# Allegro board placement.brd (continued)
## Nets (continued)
DATA1.VD3: RN3.4 U1.N1
DATA1.VD4: RN2.1 U1.P2
DATA1.VD5: RN2.2 U1.P1
DATA1.VD6: RN2.3 U1.R2
DATA1.VD7: RN2.4 U1.R1
DATA1.WSTAT_L: U1.J6 U22.11
DATA2+: U1.B5 U2.D6
DATA2-: U1.A5 U2.C6
DATA3+: U1.D5 U2.B6
DATA3-: U1.C5 U2.A6
DATA.BA0: U1.H16 U6.13 U8.2 U9.13
DATA.BA1: U1.H15 U6.14 U8.3 U9.14
DATA.BA2: U1.G14 U6.16 U8.5 U9.16
DATA.BA3: U1.G16 U6.17 U8.6 U9.17
DATA.BD0: U1.F16 U9.2
DATA.BD1: U1.F15 U9.3
DATA.BD2: U1.E16 U9.5
DATA.BD3: U1.E15 U9.6
DATA.BD4: U1.E13 U9.8
DATA.BD5: U1.E12 U9.9
DATA.BD6: U1.B15 U9.11
DATA.BD7: U1.B16 U9.12
DATA.BD8: U1.F12 U6.2 U8.23
DATA.BD9: U1.G11 U6.3 U8.22
DATA.BD12: U1.F13 U6.8 U8.17
DATA.BD13: U1.F14 U6.9 U8.16
DATA.BD14: U1.C15 U6.11 U8.14
DATA.BD15: U1.C16 U6.12 U8.13
DATA.CLKB: J6.E16 U1.J16
DDIR: U6.1 U7.1 U8.24 U9.1
DDR_A0: U2.C1 U12.M8 U13.M8
DDR_A1: U2.D1 U12.M3 U13.M3
DDR_A2: U2.E1 U12.M7 U13.M7
DDR_A3: U2.F1 U12.N2 U13.N2
DDR_A4: U2.G1 U12.N8 U13.N8
DDR_A5: U2.H1 U12.N3 U13.N3
DDR_A6: U2.J1 U12.N7 U13.N7
DDR_A7: U2.K1 U12.P2 U13.P2
DDR_A8: U2.L1 U12.P8 U13.P8
DDR_A9: U2.M1 U12.P3 U13.P3
DDR_A10: U2.N1 U12.M2 U13.M2
DDR_A11: U2.P1 U12.P7 U13.P7
DDR_A12: U2.R1 U12.R2 U13.R2
DDR_BA0: U2.M2 U12.L2 U13.L1
DDR_BA1: U2.P2 U12.L3 U13.L3
DDR_BA2: U2.R2 U12.L1 U13.L2
DDR_DQ0: U2.F5 U12.G8
DDR_DQ1: U2.C2 U12.G2
DDR_DQ2: U2.F4 U12.H7
DDR_DQ3: U2.E4 U12.H3
DDR_DQ4: U2.D3 U12.H1
DDR_DQ5: U2.G5 U12.H9
DDR_DQ6: U2.C3 U12.F1
DDR_DQ7: U2.G3 U12.F9
DDR_DQ8: U2.E2 U12.C8
DDR_DQ9: U2.B3 U12.C2
DDR_DQ10: U2.F3 U12.D7
DDR_DQ11: U2.B1 U12.D3
DDR_DQ12: U2.B2 U12.D1
DDR_DQ13: U2.F2 U12.D9
DDR_DQ14: U2.A2 U12.B1
DDR_DQ15: U2.E3 U12.B9
DDR_DQ16: U2.L3 U13.G8
DDR_DQ17: U2.H5 U13.G2
DDR_DQ18: U2.K5 U13.H7
DDR_DQ19: U2.K2 U13.H3
DDR_DQ20: U2.H3 U13.H1
DDR_DQ21: U2.L5 U13.H9
DDR_DQ22: U2.H2 U13.F1
DDR_DQ23: U2.M4 U13.F9
DDR_DQ24: U2.M5 U13.C8
DDR_DQ25: U2.J3 U13.C2
DDR_DQ26: U2.L4 U13.D7
DDR_DQ27: U2.K3 U13.D3
DDR_DQ28: U2.H4 U13.D1
DDR_DQ29: U2.N3 U13.D9
DDR_DQ30: U2.J4 U13.B1
DDR_DQ31: U2.N4 U13.B9
DDS.DATA0: U2.B10 U4.4
DDS.DATA1: U2.C10 U4.3
DDS.DATA2: U2.E10 U4.2
DDS.DATA3: U2.F10 U4.1
DDS.DATA4: U2.E11 U4.28
DDS.DATA5: U2.D11 U4.27
DDS.DATA6: U2.C11 U4.26
DDS.DATA7: U2.A11 U4.25
DDS.FQUD: U2.B12 U4.8
DDS.RESET: U2.A13 U4.22
DDS.WCLK: U2.A14 U4.7
DDS_CLK: L4.2 U4.9
DDS_OUT: C34.2 C36.2 L5.1 U4.20
DEN/: U6.48 U7.17 U9.48
DHEN/: U7.18 U8.25(G\)
DI: P1.7 U1.C12
DIFF1+: U1.D16 U6.5 U8.20
DIFF1-: U1.D14 U6.6 U8.19
DQ0: U32.19 U38.12
DQ1: U32.18 U38.13
DQ2: U32.17 U38.14
DQ3: U32.16 U38.15
DQ4: U32.15 U38.16
DQ5: U32.14 U38.17
DQ6: U32.13 U38.18
DQ7: U32.12 U38.19
DQ8: U35.19 U39.12
DQ9: U35.18 U39.13
DQ10: U35.17 U39.14
DQ11: U35.16 U39.15
DQ12: U35.15 U39.16
DQ13: U35.14 U39.17
DQ14: U35.13 U39.18
DQ15: U35.12 U39.19
FPGA/: U7.15 U48.5
GAIN: U1.J4 U33.6 U36.6
HS/: U7.16 U48.4
JTAG_D0: P1.8 U2.E14
LED1: Q4.1 R31.2
LED2: Q5.1 R32.2
LED3: Q6.1 R33.2
LED4: Q7.1 R34.2
LPF_OUT: C42.1 R17.2 R18.2
MEMORY.CTRL.RCS0: J7.26 U1.J1 U40.22 U44.22
MEMORY.CTRL.RCS1: J7.76 U1.G3 U41.22 U45.22
MEMORY.CTRL.RCS2: J7.126 U1.F2 U42.22 U46.22
MEMORY.CTRL.RCS3: J7.176 U1.G6 U43.22 U47.22
MEMORY.CTRL.RWE: J7.27 J7.77 J7.127 J7.177 U1.M11 U40.29(W\E\) U41.29(W\E\) U42.29(W\E\) U43.29(W\E\) U44.29(W\E\) U45.29(W\E\) U46.29(W\E\) U47.29(W\E\)
MEMORY.RA0: J7.1 J7.51 J7.101 J7.151 U1.P5 U40.12 U41.12 U42.12 U43.12 U44.12 U45.12 U46.12 U47.12
MEMORY.RA1: J7.2 J7.52 J7.102 J7.152 U1.P10 U40.11 U41.11 U42.11 U43.11 U44.11 U45.11 U46.11 U47.11
MEMORY.RA2: J7.3 J7.53 J7.103 J7.153 U1.N11 U40.10 U41.10 U42.10 U43.10 U44.10 U45.10 U46.10 U47.10
MEMORY.RA3: J7.4 J7.54 J7.104 J7.154 U1.R9 U40.9 U41.9 U42.9 U43.9 U44.9 U45.9 U46.9 U47.9
MEMORY.RA4: J7.5 J7.55 J7.105 J7.155 U1.P8 U40.8 U41.8 U42.8 U43.8 U44.8 U45.8 U46.8 U47.8
MEMORY.RA5: J7.6 J7.56 J7.106 J7.156 U1.R7 U40.7 U41.7 U42.7 U43.7 U44.7 U45.7 U46.7 U47.7
MEMORY.RA6: J7.7 J7.57 J7.107 J7.157 U1.P6 U40.6 U41.6 U42.6 U43.6 U44.6 U45.6 U46.6 U47.6
MEMORY.RA7: J7.8 J7.58 J7.108 J7.158 U1.N5 U40.5 U41.5 U42.5 U43.5 U44.5 U45.5 U46.5 U47.5
MEMORY.RA8: J7.9 J7.59 J7.109 J7.159 U1.L8 U40.27 U41.27 U42.27 U43.27 U44.27 U45.27 U46.27 U47.27
MEMORY.RA9: J7.10 J7.60 J7.110 J7.160 U1.M6 U40.26 U41.26 U42.26 U43.26 U44.26 U45.26 U46.26 U47.26
MEMORY.RA10: J7.11 J7.61 J7.111 J7.161 U1.T10 U40.23 U41.23 U42.23 U43.23 U44.23 U45.23 U46.23 U47.23
MEMORY.RA11: J7.12 J7.62 J7.112 J7.162 U1.P11 U40.25 U41.25 U42.25 U43.25 U44.25 U45.25 U46.25 U47.25
MEMORY.RA12: J7.13 J7.63 J7.113 J7.163 U1.T9 U40.4 U41.4 U42.4 U43.4 U44.4 U45.4 U46.4 U47.4
MEMORY.RA13: J7.14 J7.64 J7.114 J7.164 U1.T8 U40.28 U41.28 U42.28 U43.28 U44.28 U45.28 U46.28 U47.28
MEMORY.RA14: J7.15 J7.65 J7.115 J7.165 U1.T7 U40.3 U41.3 U42.3 U43.3 U44.3 U45.3 U46.3 U47.3
MEMORY.RA15: J7.16 J7.66 J7.116 J7.166 U1.T6 U40.31 U41.31 U42.31 U43.31 U44.31 U45.31 U46.31 U47.31
MEMORY.RA16: J7.17 J7.67 J7.117 J7.167 U40.2 U41.2 U42.2 U43.2 U44.2 U45.2 U46.2 U47.2
MEMORY.RD0: J7.18 J7.68 J7.118 J7.168 P2.6 U1.R15 U40.13 U41.13 U42.13 U43.13 U44.13 U45.13 U46.13 U47.13
MEMORY.RD1: J7.19 J7.69 J7.119 J7.169 P2.4 U1.R16 U40.14 U41.14 U42.14 U43.14 U44.14 U45.14 U46.14 U47.14
MEMORY.RD2: J7.20 J7.70 J7.120 J7.170 P2.2 U1.R14 U40.15 U41.15 U42.15 U43.15 U44.15 U45.15 U46.15 U47.15
MEMORY.RD3: J7.21 J7.71 J7.121 J7.171 P2.1 U1.T15 U40.17 U41.17 U42.17 U43.17 U44.17 U45.17 U46.17 U47.17
MEMORY.RD4: J7.22 J7.72 J7.122 J7.172 P2.3 U1.T14 U40.18 U41.18 U42.18 U43.18 U44.18 U45.18 U46.18 U47.18
MEMORY.RD5: J7.23 J7.73 J7.123 J7.173 P2.5 U1.T13 U40.19 U41.19 U42.19 U43.19 U44.19 U45.19 U46.19 U47.19
MEMORY.RD6: J7.24 J7.74 J7.124 J7.174 P2.7 U1.R12 U40.20 U41.20 U42.20 U43.20 U44.20 U45.20 U46.20 U47.20
MEMORY.RD7: J7.25 J7.75 J7.125 J7.175 P2.8(PIN8) U1.T12 U40.21 U41.21 U42.21 U43.21 U44.21 U45.21 U46.21 U47.21
MRD/: J6.E4 U7.8
MWR/: J6.E5 U7.9
N00036_USER_DESIGN_OUTPUTS0_D_1: L8.2 R53.1 R54.1 U32.5 U32.8 U33.5(VL)
N00036_USER_DESIGN_OUTPUTS0_DAA: L10.2 R55.1 R56.1 U35.5 U35.8 U36.5(VL)
N00038_USER_DESIGN_OUTPUTS0_D_1: C198.1 L7.2 U32.4
N00038_USER_DESIGN_OUTPUTS0_DAA: C201.1 L9.2 U35.4
N00044_USER_DESIGN_OUTPUTS0_D_1: U36.1 U37.2
N00044_USER_DESIGN_OUTPUTS0_DAA: U33.1 U34.2
N00046_USER_DESIGN_OUTPUTS0_D_1: R54.2 U33.8
N00046_USER_DESIGN_OUTPUTS0_DAA: R56.2 U36.8
N00048_USER_DESIGN_OUTPUTS0_D_1: R53.2 U33.2
N00048_USER_DESIGN_OUTPUTS0_DAA: R55.2 U36.2
N00060_USER_DESIGN_OUTPUTS0_D_1: U35.6 U37.3
N00060_USER_DESIGN_OUTPUTS0_DAA: U32.6 U34.3
PGOOD: R2012.2 U51.9
Q1E: Q9.2(E) R52.2
Q2E: C68.2 Q8.2 R45.1 R47.2
RDY/: J6.E6 U7.19
RESET: R2008.2 U1.M12 U2.T11 U49.2 U50.11
RESET/: J6.E1 U48.3
SEL: U7.11 U48.9
SHIELD1: J5.10
SHIELD2: J5.11
STDA_SSRX+: C2003.1 R2002.2 U2.A8
STDA_SSRX-: C2002.1 R2003.2 U2.B8
STDA_SSTX+: C2004.1 R2005.2 U2.E7
STDA_SSTX-: C2005.1 R2004.2 U2.E8
TCLK: P1.3 U1.C14 U2.C14
TDO: U1.E14 U2.C12
TMS: P1.11 U1.A15 U2.A15
V+12: C31.2 C32.2 C33.2 C39.2 C62.1 C64.1 C66.1 C199.1 C202.1 D5.1 J6.A1 J6.A2 J6.D1 J6.D2 R19.2 R45.2 U3.8 U5.1 U29.J1 U29.J2 U29.J3 U29.K1 U29.K2 U29.K3 U29.L1 U29.L2 U29.L3 U29.L5 U30.J1 U30.J2 U30.J3 U30.K1 U30.K2 U30.K3 U30.L1 U30.L2 U30.L3 U30.L5 U31.J1 U31.J2 U31.J3 U31.K1 U31.K2 U31.K3 U31.L1 U31.L2 U31.L3 U31.L5 U33.4 U34.7 U36.4 U37.7
VCLKC: R26.2 U39.11
VDX0: R8.2 RN2.5(2) U22.9 U38.9 U39.9 U48.11
VDX1: R6.2 RN2.6 U22.8 U38.8 U39.8 U48.12
VDX2: R4.2 RN2.7 U22.7 U38.7 U39.7 U48.13
VDX3: R2.2 RN2.8 U22.6 U38.6 U39.6 U48.14
VDX4: R7.2 RN3.5(2) U22.5 U38.5 U39.5 U48.15
VDX5: R5.2 RN3.6 U22.4 U38.4 U39.4 U48.16
VDX6: R3.2 RN3.7 U22.3 U38.3 U39.3 U48.17
VDX7: R1.2 RN3.8 U22.2 U38.2 U39.2 U48.18
VTTREF: C2016.1 U51.6
WAIT/: J6.E2 U48.2
N00286: C34.1 C35.1 C38.1 L5.2 L6.1
N00395: C35.2 C37.2 L6.2 R17.1
N00671: C3.1 R1.1
N00689: C5.1 R3.1
N00703: C7.1 R5.1
N00717: C9.1 R7.1
N00827: C4.1 R2.1
N00831: C6.1 R4.1
N00835: C8.1 R6.1
N00837: C10.1 R8.1
N04966: L7.1 L9.1
N15853: U2.T7 U12.K9
N15863: U2.R7 U13.K9
N15891: U2.M7 U12.B3
N15907: U2.P6 U12.F3
N15924: U2.N6 U13.F3
N15963: U2.L7 U13.B3
N16041: U2.T5 U12.J8 U13.J8
N16054: U2.R5 U12.K8 U13.K8
N16064: U2.T4 U12.K2 U13.K2
N16300: U2.P5 U12.L8
N16316: U2.N5 U13.L8
N16670: U2.P8 U12.K3 U13.K3
N16714: U2.P7 U12.K7 U13.K7
N16747: U2.T3 U12.L7 U13.L7
N17275: U2.R9 U12.B7
N17319: U2.T9 U12.A8
N17344: U2.N9 U13.A8
N17369: U2.P9 U13.B7
N17394: U2.M6 U12.F7
N17449: U2.T6 U13.F7
N44457: U1.K6 U10.8
N44464: U1.K3 U10.3 U10.13
N44478: U1.E2 U10.7
N44485: U1.L4 U10.10
N44490: U1.L5 U10.1
N45317: U2.M11 U11.1
N61996: C71.1 R50.2
N62056: Q8.1 R46.1 R51.1
N62230: C71.2 Q9.1 R48.1 R49.1
N62316: C72.2 Q8.3(E) R48.2
N62436: D5.3(C) R46.2
N62564: C69.1 C70.1 Q9.3 R47.1
N68133: C42.2 Q3.1 R21.1 R23.2
N70364: C43.2 Q3.2(E) R24.2
N80550: C40.2 R19.1
N81780: C69.2 R49.2
N84247: U6.22 U8.9 U8.12 U9.20
N103899: U6.19 U6.23 U8.8 U8.11 U9.19 U9.23
N108857: R12.2 U4.21
N108997: R14.2 U4.12
N111502: C11.1 C12.2 U3.1(OUT)
N111881: C11.2 C13.2 C14.2 R9.2 R10.2 R11.1
N113142: C15.2 L4.1 R9.1
N114006: C18.1 C20.1 Q1.1 R10.1 R13.2
N118214: C19.1 L3.3(OUT2) Q1.3
N118917: C16.2 L3.1 R11.2
N120412: C17.1 L3.2
N121910: C20.2 C21.2 Q1.2(E) R15.2
N123723: C17.2 Q2.3 R16.2
N124926: C19.2 C21.1 C22.2 Q2.1 R13.1 R15.1 R16.1 XTAL1.3
N129422: C22.1 L4.3(OUT2) Q2.2(S)
N221560: C18.2 XTAL1.4
N277989: Q3.3
N828385: R31.1 U22.19
N829333: R43.1 U31.G7
N829669: R44.1 U31.K7
N829685: U31.G5 U31.H5
N830942: D3.A R29.2
N831005: D3.C Q6.3
N831029: R39.1 U29.G7
N831181: R40.1 U29.K7
N831646: D2.A R28.2
N831650: D2.C Q5.3
N831853: R41.1 U30.G7
N831855: D1.A R27.2
N831859: D1.C Q4.3
N832005: R42.1 U30.K7
N832074: D4.A R30.2
N832078: D4.C Q7.3
N852308: R32.1 U22.17
N852494: R33.1 U22.15
N852683: R34.1 U22.13
N884986: C70.2 J3.1
N885188: C2.1 J2.1 L2.2
N885276: C1.1 J1.1 L1.2
N885442: L1.1 U34.6
N1358395: J5.6 R2003.1
N1358407: J5.8 R2004.1
N1358411: J5.9 R2005.1
N1358515: J5.2 R2000.1
N1358527: J5.3 R2001.1
N1358539: J5.5 R2002.1
N1406173: R2009.1 U50.9(XTAL2) Y1.3(OUTPUT)
N1406200: R2009.2 U50.8 Y1.1
N1406547: C2008.1 C2009.1 R2006.2 U50.4 U50.5
N1406997: R2007.1 U50.10 U50.19 U50.21
N1421557: L2.1 U37.6
N1432081: U2.M12 U11.8
N1432096: U2.R11 U11.3
N1432111: U2.P10 U11.7
N1432121: U2.T10 U11.10
N1438447: SW2.2 U49.3
N1472359: C2010.1 R2010.2 R2011.1 U51.1
N2993541: C43.1 R25.2

Pads without a net: D5 2; J6 A5 A6 A7 A8 A9 A10 A11 A12 A13 A14 A15 A16 A17 A18 A19 A20 A21 A22 C3 C4 C5 C6 C7 C8 C9 C10 C11 C12 C13 C14 C15 C16 C17 C18 C19 C20 C21 C22 D5 D6 D7 D8 D9 D10 D11 D12 D13 D14 D15 D16 D17 D18 D19 D20 D21 D22 E7 F3 F4 F5 F6 F7 F8 F9 F10 F11 F12 F13 F14 F15 F16 F17 F18 F19 F20 F21 F22; J7 28 29 30 78 79 80 128 129 130 178 179 180; P1 10; SW2 3 4; U1 A2 A3 A4 A7 A8 A9 A10 A11 A12 A13 A14 B1 B2 B3 B8 B10 B12 B14 C1 C2 C4 C7 C8 C9 C10 C11 C13 D1 D3 D8 D9 D11 D12 E1 E3 E4 E6 E7 E8 E10 E11 F1 F3 F4 F5 F6 F7 F9 F10 G1 G5 G12 H1 H2 H5 H11 H13 H14 J3 J11 J12 J13 J14 K1 K2 K11 K12 K14 K15 K16 L1 L3 L7 L10 L11 L12 L13 L14 L16 M3 M4 M5 M7 M10 M13 M14 M15 M16 N4 N6 N9 N12 N14 N16 P4 P7 P9 P12 P13 P14 P15 P16 R3 R5 T2 T3 T4 T5; U2 A3 A4 A7 A9 A10 A12 B14 B15 B16 C4 C7 C8 C9 C13 C15 C16 D8 D9 D12 D14 D16 E6 E12 E13 E15 E16 F6 F7 F9 F12 F13 F14 F15 F16 G6 G11 G12 G14 G16 H11 H13 H14 H15 H16 J6 J13 J14 J16 K6 K11 K12 K14 K15 K16 L8 L10 L11 L12 L13 L14 L16 M3 M9 M10 M13 M14 M15 M16 N8 N12 N14 N16 P4 P12 P13 P14 P15 P16 R3 R12 R14 R15 R16 T2 T8 T12 T13 T14 T15; U3 4 5; U4 13 14 15 16 17; U6 20; U9 22; U10 2 4 5 6 9 12 14 15 16 17; U11 2 4 5 6 9 12 13 14 15 16 17; U12 A2 E2 E8 G3 R3 R7 R8; U13 A2 E2 E8 G3 R3 R7 R8; U22 12 14 16 18; U29 G5 H7 J7; U30 G5 H7 J7; U31 H7 J7; U34 1 5 8; U37 1 5 8; U40 1 30; U41 1 30; U42 1 30; U43 1 30; U44 1 30; U45 1 30; U46 1 30; U47 1 30; U48 1 19; U50 6 7 16 24 26; XTAL1 5; Y1 2 4

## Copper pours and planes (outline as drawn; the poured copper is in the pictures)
GND EARTH on TOP (solid shape): 124.87,24.04 124.87,16.51 117.25,16.51 117.25,19.05 119.64,19.05 122.97,20.32 119.64,21.59 117.63,21.59 116.26,20.23 114.23,20.23 114.23,24.04 114.48,24.29 124.62,24.29
GND EARTH on TOP (solid shape): 124.87,8.56 124.87,1.04 117.25,1.04 117.25,3.58 119.64,3.58 122.97,4.85 119.64,6.12 117.63,6.12 116.26,4.75 114.23,4.75 114.23,8.56 114.48,8.81 124.62,8.81
Net_5 on TOP (solid shape): 9.62,107.11 9.63,107.07 9.63,107 9.63,106.88 9.63,106.17 9.63,104.94 9.64,103.66 9.64,103.53 9.65,103.38 9.63,103.21 9.61,103.19 9.56,103.19 9.44,103.19 9.26,103.18 9.05,103.18 8.83,103.18 8.43,103.19 8.22,103.19 7.5,104.25 7.49,104.43 7.48,104.59 7.48,104.71 8.13,104.71 8.13,104.67 8.21,104.1 8.23,104.03 8.26,103.97 8.29,103.91 8.32,103.86 8.35,103.81 8.39,103.77 8.48,103.71 8.88,103.67 8.95,103.73 8.95,105.29 8.92,105.38 8.81,105.59 8.75,105.64 8.7,105.7 8.61,105.7 8.54,105.7 8.43,105.66 8.38,105.61 8.35,105.58 8.32,105.55 8.3,105.51 8.27,105.47 8.25,105.43 8.24,105.39 8.22,105.35 8.16,105 8.13,104.75 8.13,104.71 7.48,104.71 7.48,104.79 7.48,104.88 7.49,104.96 7.49,105.04 7.5,105.1 7.5,105.16 7.52,105.26 8.91,106.08 8.95,106.36 8.95,107.09 9.49,107.16
Net_6 on TOP (solid shape): 5.7,106.11 6,105.59 6.05,105.42 6.06,103.98 6.06,103.84 6.06,103.72 6.06,103.46 6.09,103.28 6.09,103.25 6.08,103.22 6.05,103.2 6,103.19 5.91,103.19 5.78,103.18 5.16,103.18 4.98,103.18 4.84,103.19 4.74,103.19 4.66,103.2 4.6,103.21 4.56,103.22 4.47,103.26 4.42,103.29 4.38,103.32 4.34,103.34 4.31,103.38 4.27,103.41 4.22,103.48 4.17,103.56 4.05,104.09 4.05,104.13 4.69,104.13 4.69,104.08 4.71,103.97 5.06,103.67 5.16,103.67 5.24,103.67 5.35,103.7 5.38,103.73 5.4,103.99 5.4,104.44 5.39,104.68 5.38,104.7 5.22,104.72 5.16,104.71 4.77,104.47 4.74,104.43 4.73,104.39 4.71,104.35 4.7,104.3 4.69,104.24 4.69,104.19 4.69,104.13 4.05,104.13 4.06,104.26 4.08,104.39 4.15,104.57 4.19,104.65 5.04,105.15 5.09,105.16 5.37,105.33 5.35,105.41 5.34,105.47 5.31,105.53 5.29,105.59 5.25,105.63 5.21,105.67 5.17,105.7 5.06,105.75 4.99,105.77 4.86,105.77 4.78,105.76 4.29,105.66 4.29,106.04 4.34,106.07
Net_7 on TOP (solid shape): 2.6,106.24 2.67,106.23 2.84,105.87 2.82,105.68 2.51,105.7 2.38,105.7 2.28,105.65 1.87,105.07 1.86,105.04 1.85,104.91 1.84,104.76 1.85,104.46 1.85,104.4 1.86,104.32 1.88,104.26 2.06,103.88 2.17,103.8 2.24,103.76 2.34,103.71 2.75,103.74 2.78,103.74 2.8,103.73 2.82,103.72 2.83,103.7 2.83,103.66 2.84,103.61 2.84,103.46 2.81,103.22 2.78,103.2 2.39,103.16 1.58,103.44 1.5,103.51 1.16,104.76 1.25,105.29 1.51,105.79 1.54,105.83 1.62,105.91 1.67,105.96 1.76,106.03 1.82,106.08 2.18,106.23 2.25,106.24
Net_8 on TOP (solid shape): outline of 83 points within 11.04,103.15 13.13,106.24
Net_9 on TOP (solid shape): 19.34,106.24 19.45,106.24 19.53,106.23 19.6,106.22 19.64,106.2 19.67,106.18 19.7,106.14 19.7,106.08 19.71,105.92 19.57,105.68 19.45,105.7 19.36,105.7 19.27,105.69 19.19,105.68 19.12,105.65 19.06,105.61 19.03,105.59 18.96,105.52 18.91,105.46 18.7,104.77 18.7,104.64 18.7,104.52 18.72,104.37 18.79,104.13 18.81,104.09 18.83,104.04 18.86,103.99 18.89,103.94 18.92,103.9 18.96,103.86 19.02,103.81 19.28,103.7 19.71,103.7 19.71,103.45 19.71,103.34 19.7,103.3 19.7,103.27 19.68,103.25 19.67,103.23 19.63,103.21 19.58,103.19 19.52,103.18 19.45,103.17 19.37,103.16 19.29,103.16 19.21,103.16 19.13,103.16 18.97,103.17 18.57,103.33 18.38,103.51 18.17,103.85 18.05,104.4 18.04,104.54 18.04,104.68 18.04,104.81 18.33,105.73 18.39,105.81 18.43,105.85 18.51,105.94 18.64,106.05 18.74,106.12 19.25,106.24
Net_10 on TOP (solid shape): 22.16,106.24 22.24,106.23 22.96,105.06 22.97,104.88 22.96,104.68 22.77,104.53 22.58,104.52 22.23,104.52 21.58,104.52 21.66,103.93 21.69,103.9 21.72,103.86 21.75,103.83 21.78,103.8 21.83,103.77 21.87,103.75 21.97,103.7 22.68,103.73 22.72,103.73 22.75,103.73 22.77,103.71 22.78,103.68 22.78,103.64 22.6,103.22 22.54,103.2 22.49,103.19 22.42,103.18 22.34,103.17 22.18,103.16 22.02,103.16 21.9,103.16 21.65,103.21 21.45,103.3 21.38,103.35 21.26,103.47 21.18,103.56 21.04,103.77 20.92,104.18 20.87,104.71 20.88,104.77 20.92,105.09 21.55,105.09 21.57,105.01 21.59,104.99 21.62,104.99 21.78,104.99 21.99,104.99 22.19,104.99 22.29,105 22.34,105.24 22.08,105.72 22.05,105.74 22.03,105.75 22,105.75 21.97,105.75 21.93,105.75 21.9,105.74 21.66,105.54 21.61,105.42 21.58,105.33 21.57,105.29 21.56,105.21 21.55,105.09 20.92,105.09 21.13,105.73 21.38,106.03 21.44,106.07 22.04,106.24
Net_11 on TOP (solid shape): 16.02,106.23 16.51,105.82 16.61,105.49 16.62,105.44 16.62,105.38 16.63,105.3 16.63,105.19 16.63,105.05 16.64,104.88 16.64,104.67 16.64,104.13 16.64,103.88 16.64,103.67 16.64,103.52 16.63,103.32 16.63,103.23 16.62,103.2 16.46,103.18 16.09,103.19 16.05,103.19 16.02,103.2 16,103.21 15.98,103.22 15.97,103.25 15.97,103.51 15.97,103.63 15.97,103.77 15.97,103.92 15.97,104.26 15.97,105.24 15.58,105.69 15.25,105.69 15.22,105.63 15.21,105.59 15.21,105.42 15.21,105.06 15.21,103.23 14.58,103.22 14.57,103.33 14.57,103.44 14.56,103.59 14.56,103.81 14.56,104.47 14.56,104.91 14.55,105.13 14.64,106.23 14.76,106.23 15.31,106.23

Small or netless copper shapes (teardrops, artwork), in the pictures only: 2 on TOP
